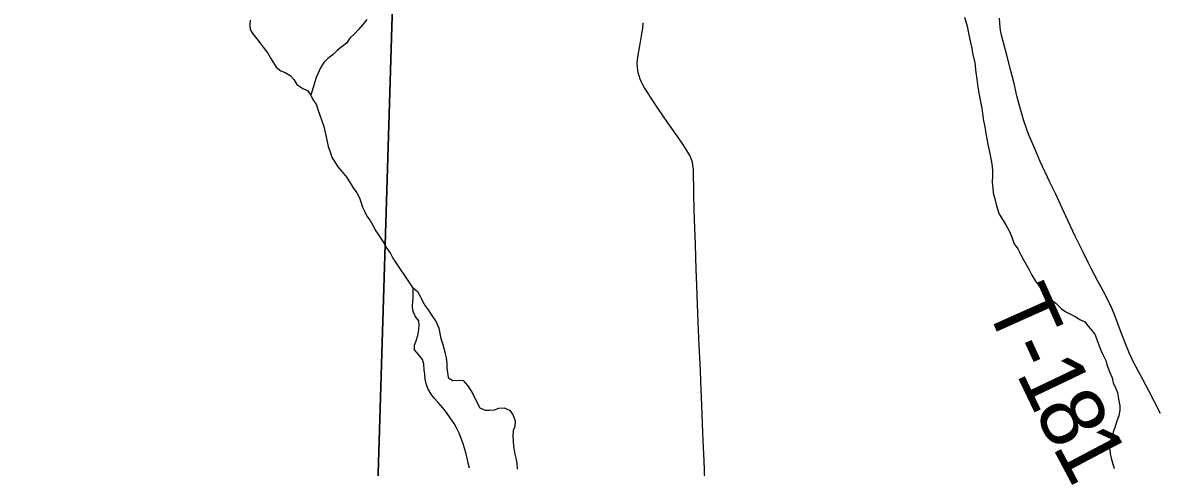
# Model space of a CAD drawing. Extents: x -7.9 to 76.1, y 0 to 22.
# Drawn here: x 3.119 to 4.139, y 19.828 to 20.222 of the extents above; entities that cross this region are included whole.
import ezdxf

# ---------------------------------------------------------------- set-up
doc = ezdxf.new("R2010")
doc.units = 0
for name, color, linetype in [('GM_X_County_Road', 7, 'Continuous'), ('GM_X_Minor_Lake', 7, 'Continuous'), ('GM_X_Minor_River', 7, 'Continuous'), ('GM_X_Section', 7, 'Continuous'), ('GM_X_Township_Road', 7, 'Continuous'), ('GM_X_Township_Road_Text', 7, 'Continuous')]:
    doc.layers.add(name, color=color, linetype=linetype)

msp = doc.modelspace()

# ---------------------------------------------------------------- linework, layer by layer
at = {"layer": 'GM_X_County_Road'}
msp.add_lwpolyline([(3.7235, 19.8162), (3.7228, 19.8338), (3.7221, 19.851), (3.7212, 19.8743), (3.7205, 19.8902), (3.72, 19.9034), (3.7196, 19.9146), (3.7185, 19.9356), (3.7175, 19.9568), (3.717, 19.9723), (3.7164, 19.9893), (3.7159, 20.0033), (3.7151, 20.0254), (3.7146, 20.0399), (3.714, 20.0562), (3.7136, 20.0707), (3.7133, 20.0924), (3.7129, 20.0959), (3.7124, 20.0984), (3.7116, 20.1009), (3.7104, 20.1039), (3.7083, 20.1075), (3.7039, 20.1146), (3.6986, 20.1221), (3.6907, 20.1335), (3.6817, 20.1466), (3.6748, 20.157), (3.6734, 20.1592), (3.67, 20.1645), (3.6685, 20.1671), (3.6674, 20.1695), (3.6661, 20.1723), (3.6652, 20.1751), (3.6644, 20.1777), (3.6639, 20.1801), (3.6636, 20.1829), (3.6634, 20.1862), (3.6636, 20.1894), (3.6642, 20.1934), (3.6657, 20.2018), (3.6676, 20.2124), (3.6684, 20.2176), (3.6687, 20.2222)], dxfattribs=at)
at = {"layer": 'GM_X_Minor_Lake'}
for points in [[(3.5147, 19.8269), (3.5135, 19.8314), (3.5127, 19.8356), (3.5119, 19.8394), (3.5103, 19.8446), (3.5091, 19.8484), (3.5071, 19.8541), (3.5055, 19.8578), (3.5031, 19.8627), (3.5012, 19.8665), (3.4981, 19.8706), (3.4942, 19.8762), (3.4911, 19.8803), (3.4869, 19.8852), (3.4834, 19.8889), (3.4807, 19.8926), (3.4779, 19.8975), (3.4763, 19.902), (3.4755, 19.9058), (3.4751, 19.9104), (3.4746, 19.9141), (3.4742, 19.9191), (3.473, 19.9232), (3.4695, 19.9277), (3.466, 19.9318), (3.4659, 19.936), (3.4674, 19.9398), (3.4688, 19.9447), (3.4698, 19.9497), (3.4702, 19.9539), (3.4697, 19.9576), (3.4666, 19.9618), (3.4646, 19.9667), (3.4642, 19.9708), (3.4648, 19.9788), (3.4647, 19.9871), (3.4685, 19.9838), (3.4712, 19.9789), (3.4732, 19.9751), (3.4755, 19.971), (3.4782, 19.9673), (3.4814, 19.9624), (3.4852, 19.9568), (3.4876, 19.9511), (3.4893, 19.9421), (3.4909, 19.9375), (3.4921, 19.9334), (3.4933, 19.9285), (3.4941, 19.9247), (3.4946, 19.9198), (3.4946, 19.916)], [(3.4946, 19.916), (3.4951, 19.9118), (3.4959, 19.9073), (3.4998, 19.9047), (3.5088, 19.9049), (3.5131, 19.9004), (3.5158, 19.8959), (3.5181, 19.8922), (3.5209, 19.8861), (3.524, 19.8805), (3.5286, 19.8783), (3.5324, 19.8784), (3.5369, 19.8788), (3.5407, 19.88), (3.5456, 19.8805), (3.5502, 19.8783), (3.5533, 19.8746), (3.5552, 19.8689), (3.555, 19.864), (3.5535, 19.8602), (3.5532, 19.8556), (3.5537, 19.8465), (3.555, 19.8394), (3.5558, 19.8356), (3.5566, 19.8314), (3.5571, 19.8261)]]:
    msp.add_lwpolyline(points, dxfattribs=at)
at = {"layer": 'GM_X_Minor_River'}
for points in [[(3.9539, 20.2273), (3.956, 20.2194), (3.9572, 20.213), (3.9584, 20.2073), (3.9601, 20.2009), (3.9613, 20.1941), (3.963, 20.1866), (3.9639, 20.1782), (3.9647, 20.1722), (3.9656, 20.165), (3.9669, 20.1582), (3.9681, 20.1522), (3.969, 20.1465), (3.9698, 20.1416), (3.9707, 20.1351), (3.9715, 20.1314), (3.9732, 20.1208), (3.9748, 20.1129), (3.9761, 20.1061), (3.9773, 20.1), (3.9782, 20.0951), (3.9786, 20.0906), (3.9787, 20.0864), (3.9784, 20.0807), (3.9789, 20.0754), (3.9793, 20.0712)], [(3.3202, 20.2245), (3.3199, 20.2207), (3.3203, 20.2162), (3.3226, 20.2125), (3.3261, 20.208), (3.3292, 20.2042), (3.3316, 20.2005), (3.3358, 20.1952), (3.3385, 20.1907), (3.3409, 20.1866), (3.3432, 20.1829), (3.3474, 20.1795), (3.3512, 20.1781), (3.3558, 20.1755), (3.3589, 20.1718), (3.3616, 20.1676), (3.367, 20.164), (3.3712, 20.1621), (3.3739, 20.158), (3.3759, 20.1543), (3.379, 20.1494), (3.3802, 20.1452), (3.3834, 20.1362), (3.3854, 20.1302), (3.387, 20.1237), (3.3886, 20.1169), (3.3895, 20.1124), (3.3915, 20.1068), (3.3926, 20.103), (3.395, 20.0992), (3.3981, 20.0944), (3.4016, 20.0903), (3.4058, 20.085), (3.4089, 20.0802), (3.4117, 20.0757), (3.4148, 20.0712)], [(3.4238, 20.2252), (3.4201, 20.2206), (3.4164, 20.2164), (3.4127, 20.2125), (3.4086, 20.2087), (3.4057, 20.2041), (3.4019, 20.2013), (3.3978, 20.1979), (3.3937, 20.194), (3.3892, 20.1905), (3.3855, 20.187), (3.3826, 20.1824), (3.3804, 20.1775), (3.3786, 20.1736), (3.3739, 20.158)], [(3.4148, 20.0712), (3.4171, 20.067), (3.4187, 20.0625), (3.4199, 20.0587), (3.4215, 20.055), (3.4238, 20.0505), (3.4265, 20.0467), (3.4289, 20.0426), (3.4308, 20.0388), (3.434, 20.034), (3.4371, 20.0295), (3.4394, 20.0257), (3.4417, 20.0216), (3.4448, 20.0175), (3.4468, 20.0133), (3.4647, 19.9864)], [(3.9793, 20.0712), (3.9806, 20.0659), (3.9822, 20.0599), (3.9846, 20.0524), (3.9881, 20.0467), (3.9908, 20.0422), (3.9932, 20.0381), (3.9955, 20.0329), (3.9979, 20.0261), (4.001, 20.0216), (4.0037, 20.0163), (4.0061, 20.0118), (4.0108, 20.0036), (4.0135, 19.9983), (4.0166, 19.993), (4.0194, 19.9893), (4.0225, 19.9848), (4.0278, 19.9804), (4.0305, 19.9762), (4.0348, 19.9733), (4.0398, 19.9684), (4.0436, 19.9658), (4.052, 19.9614), (4.0562, 19.9589), (4.0604, 19.9567), (4.0635, 19.9529), (4.067, 19.9488), (4.0697, 19.9451), (4.0713, 19.9402), (4.0748, 19.9315), (4.0764, 19.9278), (4.0792, 19.9225), (4.0804, 19.918), (4.0827, 19.9119), (4.0847, 19.9071), (4.0856, 19.9025), (4.0879, 19.8976), (4.0895, 19.8939), (4.0903, 19.8882), (4.0916, 19.8822), (4.0916, 19.8784), (4.0906, 19.8734), (4.0892, 19.8696), (4.087, 19.8631), (4.0856, 19.8589), (4.0849, 19.8547), (4.0831, 19.8502), (4.0824, 19.8452), (4.0829, 19.8399), (4.0837, 19.8358), (4.0849, 19.8316), (4.0865, 19.8267)]]:
    msp.add_lwpolyline(points, dxfattribs=at)
at = {"layer": 'GM_X_Section'}
for points in [[(3.4482, 20.2963), (3.4168, 19.2711), (2.4057, 19.2962), (2.4291, 20.3209)], [(4.4641, 20.2762), (4.4336, 19.2503), (3.4168, 19.2711), (3.4482, 20.2963)]]:
    msp.add_lwpolyline(points, close=True, dxfattribs=at)
at = {"layer": 'GM_X_Township_Road'}
msp.add_lwpolyline([(4.1276, 19.8754), (4.1223, 19.8857), (4.1172, 19.8954), (4.1118, 19.9056), (4.1077, 19.9132), (4.1035, 19.9215), (4.1001, 19.9286), (4.0974, 19.9351), (4.0929, 19.9464), (4.0864, 19.964), (4.084, 19.9696), (4.0812, 19.9756), (4.0767, 19.9842), (4.0721, 19.9929), (4.0665, 20.0036), (4.0634, 20.0095), (4.0586, 20.0193), (4.052, 20.0329), (4.0458, 20.0462), (4.0405, 20.0577), (4.0347, 20.07), (4.0295, 20.0809), (4.0209, 20.0991), (4.0164, 20.1098), (4.0106, 20.1235), (4.0064, 20.1351), (4.0048, 20.1406), (4.0027, 20.1477), (4.0001, 20.1573), (3.9977, 20.1684), (3.995, 20.1797), (3.9914, 20.1936), (3.9881, 20.2057), (3.9867, 20.2113), (3.9858, 20.2158), (3.9853, 20.2184), (3.985, 20.2218), (3.9847, 20.2264)], dxfattribs=at)

# ---------------------------------------------------------------- texts
at = {"layer": 'GM_X_Township_Road_Text'}
for s, rotation, p in [('T', 294.1187, (3.9715, 19.9725)), ('-', 294.5208, (3.989, 19.9333)), ('1', 295.5587, (3.9992, 19.9111)), ('8', 296.8124, (4.0149, 19.8783)), ('1', 297.8754, (4.0312, 19.846))]:
    msp.add_text(s, height=0.0568, rotation=rotation, dxfattribs=at).set_placement(p)

doc.saveas('drawing.dxf')
